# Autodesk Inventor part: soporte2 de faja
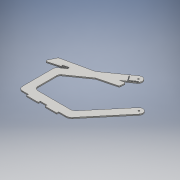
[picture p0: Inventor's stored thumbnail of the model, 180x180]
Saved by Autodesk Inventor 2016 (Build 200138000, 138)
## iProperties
Created: 2016-06
Part Number: soporte2 de faja
Material: Genérico
Document SubType Name: Modeling
Designer: adm
Density: 1 g/cm^3
Appearance: Valor por defecto
Author: adm
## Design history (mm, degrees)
sketch "Boceto1"
  geometry: L1 (-172.816, -58.403)-(-70.881, 13.642); L2 (-99.407, 42.463)-(-226.174, 14.411); L3 (-99.407, 42.463)-(-253.277, 8.414); L4 (-201.273, -230.979)-(-169.73, -230.979); L5 (-181.273, -74.736)-(-181.273, -170.979); L6 (-221.273, -54.025)-(-221.273, -210.979); L7 (-181.273, -15.398)-(-212.816, -37.692); L8 (-211.978, -14.169)-(-210.451, -19.972); L9 (-183.373, -12.849)-(-210.451, -19.972); L10 (-183.373, -12.849)-(-184.899, -7.046); L11 (-211.978, -14.169)-(-184.899, -7.046); L12 (-184.899, -7.046)-(-211.978, -14.169); L13 (-210.451, -19.972)-(-183.373, -12.849); L14 (-269.159, -38.518)-(-181.273, -15.398); L15 (-256.687, 5.732)-(-274.921, -31.482); L16 (23.163, 83.783)-(25.776, 85.63); L17 (25.776, 85.63)-(23.163, 83.783); L18 (25.677, 89.234)-(27.524, 86.621); L19 (25.677, 89.234)-(27.524, 86.621); L20 (32.301, 89.997)-(27.524, 86.621); L21 (55.109, 102.688)-(28.977, 84.219); L22 (27.524, 86.621)-(56.106, 106.822); L23 (22.169, 69.365)-(1.485, 64.788); L24 (22.169, 69.365)-(1.485, 64.788); L25 (25.677, 89.234)-(54.259, 109.435); L26 (1.485, 64.788)-(55.109, 102.688); L27 (8.461, 110.129)-(25.776, 85.63); L28 (5.847, 108.282)-(23.163, 83.783); L29 (8.461, 110.129)-(5.847, 108.282); L30 (-15.003, -240.979)-(-15.003, -230.979); L31 (-15.003, -240.979)-(-15.003, -230.979); L32 (-15.003, -230.979)-(22.302, -230.979); L33 (201.715, -33.835)-(45.284, -220.263); L34 (45.284, -220.263)-(201.715, -33.835); L35 (171.073, -8.123)-(26.631, -180.263); L36 (54.259, 109.435)-(56.106, 106.822); L37 (57.428, 104.605)-(57.559, 104.42); L38 (-70.881, 13.642)-(22.812, 38.289); L39 (-70.881, 13.642)-(22.812, 38.289); L40 (32.022, 135.353)-(-99.407, 42.463); L41 (32.022, 135.353)-(-99.407, 42.463); L42 (26.532, 42.84)-(27.743, 64.115); L43 (26.532, 42.84)-(27.743, 64.115); L44 (-169.73, -230.979)-(-169.73, -240.979); L45 (-169.73, -230.979)-(-169.73, -240.979); L46 (-169.73, -230.979)-(-169.73, -240.979); L47 (-169.73, -240.979)-(-109.73, -240.979); L48 (-169.73, -240.979)-(-109.73, -240.979); L49 (-109.73, -240.979)-(-109.73, -230.979); L50 (-109.73, -240.979)-(-109.73, -230.979); L51 (-109.73, -240.979)-(-109.73, -230.979); L52 (-109.73, -230.979)-(-75.003, -230.979); L53 (-109.73, -230.979)-(-75.003, -230.979); L54 (-75.003, -230.979)-(-75.003, -240.979); L55 (-75.003, -230.979)-(-75.003, -240.979); L56 (-161.273, -190.979)-(3.65, -190.979); L57 (-75.003, -240.979)-(-15.003, -240.979); L58 (-75.003, -240.979)-(-15.003, -240.979); C1 r 3.25 at (186.394, -20.979); C2 r 3.75 at (186.394, -20.979); C3 r 3.75 at (43.566, 119.021); A1 r 20 centre (-161.273, -74.736) between (-172.816, -58.403) and (-181.273, -74.736); A2 r 20 centre (-161.273, -170.979) between (-181.273, -170.979) and (-161.273, -190.979); A3 r 20 centre (-201.273, -210.979) between (-221.273, -210.979) and (-201.273, -230.979); A4 r 20 centre (-201.273, -54.025) between (-212.816, -37.692) and (-221.273, -54.025); A5 r 5 centre (-252.197, 3.532) between (-253.277, 8.414) and (-256.687, 5.732); A6 r 5 centre (-270.431, -33.682) between (-274.921, -31.482) and (-269.159, -38.518); A7 r 30 centre (3.65, -160.979) between (3.65, -190.979) and (26.631, -180.263); A8 r 30 centre (3.65, -160.979) between (3.65, -190.979) and (26.631, -180.263); A9 r 30 centre (22.302, -200.979) between (22.302, -230.979) and (45.284, -220.263); A10 r 30 centre (22.302, -200.979) between (22.302, -230.979) and (45.284, -220.263); A11 r 20 centre (186.394, -20.979) between (201.715, -33.835) and (171.073, -8.123); A12 r 20 centre (43.566, 119.021) between (55.109, 102.688) and (32.022, 135.353); A13 r 5 centre (22.751, 64.399) between (27.743, 64.115) and (22.169, 69.365); A14 r 5 centre (22.751, 64.399) between (27.743, 64.115) and (21.183, 69.147); A15 r 5 centre (21.54, 43.125) between (22.812, 38.289) and (26.532, 42.84); A16 r 5 centre (21.54, 43.125) between (22.812, 38.289) and (26.532, 42.84); 8 further points
  constraints: 119 end point, 36 point on circle, 19 centre point, 14 point on line, 14 tangent, 10 parallel, 7 coincident, 7 collinear, 6 perpendicular, 3 vertical, 2 horizontal
  dimensions: "d0" = 40 distance between parallel lines of L5 L6; "d1" = 20 radius of A2; "d2" = 20 radius of A3; "d3" = 20 radius of A1; "d4" = 20 radius of A4; "d5" = 7.5 diameter of C2; "d6" = 160 distance of L2.start point (-255.628, 7.894); "d7" = 7.5 diameter of C3; "d8" = 5 radius of A5; "d9" = 5 radius of A6; "d10" = 10 distance between parallel lines of L47 L4; "d11" = 10 distance between parallel lines of L52 L57; "d12" = 3.2 distance between parallel lines of L27 L28; "d13" = 2 distance between parallel lines of L27 L18; "d16" = 3.2 distance between parallel lines of L22 L25
extrude "Extrusión1" new body sketch "Boceto1" distance "d14" = 6; taper "d15" = 0 deg
node "Sólido1"
